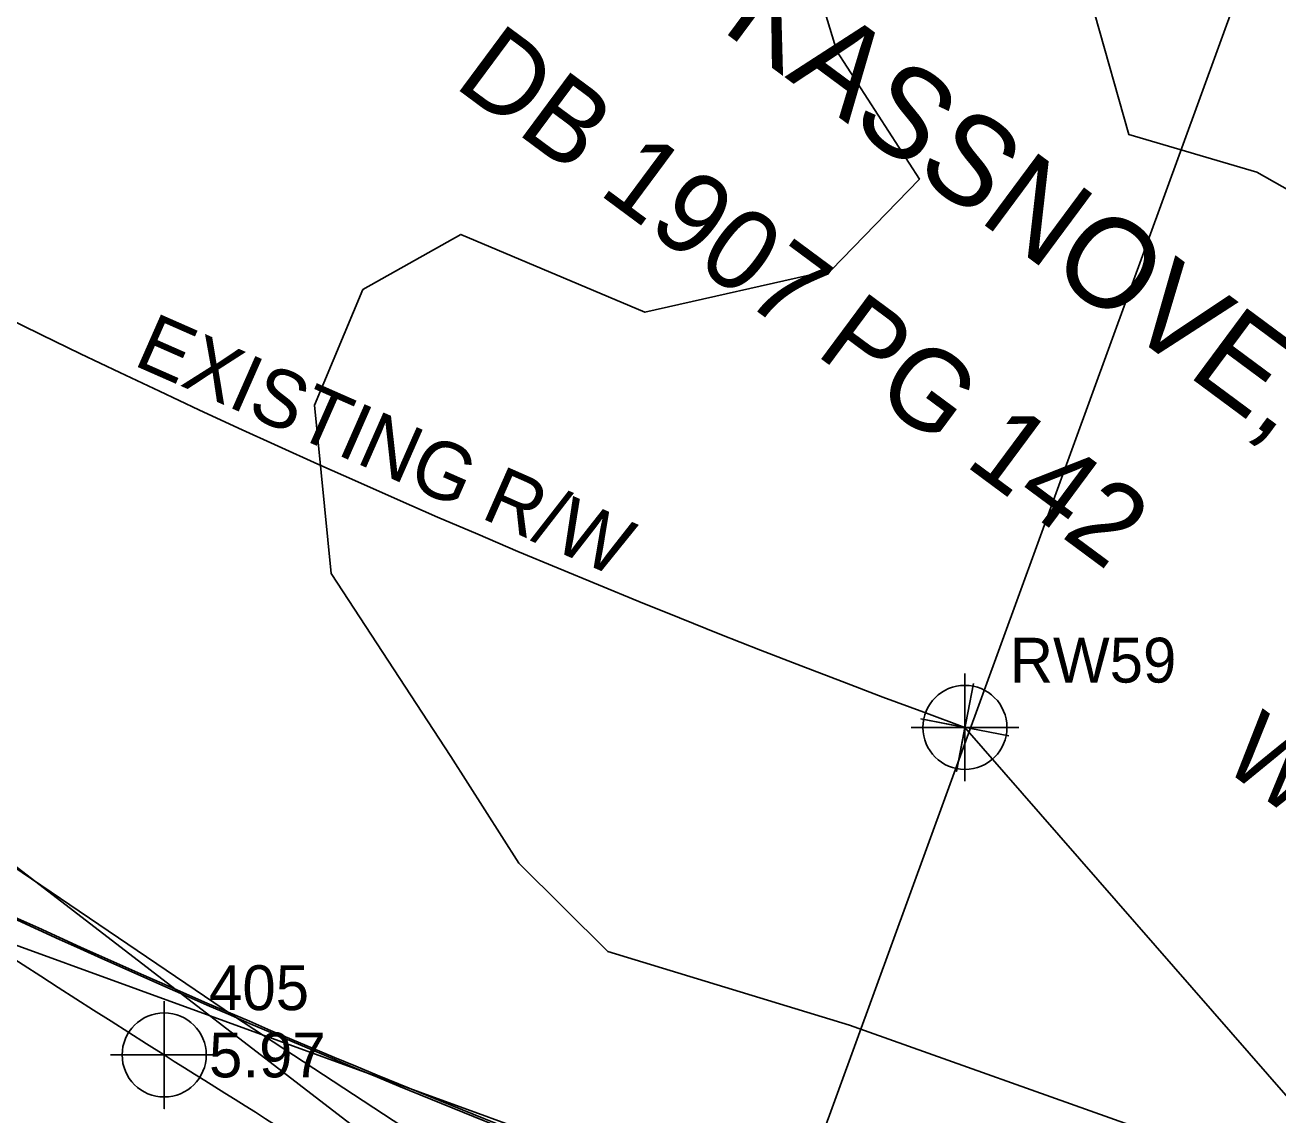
# Model space of a CAD drawing. Extents: x 2597630 to 2605918, y 617194 to 635093.
# Drawn here: x 2605095.9 to 2605165.7, y 618524 to 618584.8 of the extents above; entities that cross this region are included whole.
import ezdxf

# ---------------------------------------------------------------- set-up
doc = ezdxf.new("R2010")
doc.units = 0
for name, color, linetype in [('COGO Default Chain', 7, 'Continuous'), ('COGO Default Curve', 7, 'Continuous'), ('Cogo Default Point CELL', 7, 'Continuous'), ('COGO Default Point Number', 7, 'Continuous'), ('Exist Horizontal Alignment', 7, 'Continuous'), ('Exist Property Corner CELL', 7, 'Continuous'), ('Exist Property Deed Book Text', 7, 'Continuous'), ('Exist Property Owner Text', 7, 'Continuous'), ('Exist Right of Way Line', 7, 'Continuous'), ('Exist Right of Way Line Text', 7, 'Continuous'), ('Exist Roads EOP', 7, 'Continuous'), ('Exist Roads EOP Cogo Elevation', 7, 'Continuous'), ('Exist Roads EOP Cogo Number', 7, 'Continuous'), ('Exist Roads EOP Cogo Point CELL', 7, 'Continuous'), ('Exist Utilities Telephone UG Cable SUE LOS C', 7, 'Continuous'), ('Exist Vegetation Woods Line', 7, 'Continuous'), ('Exist Vegetation Woods Line Text', 7, 'Continuous'), ('Raster_Level_3', 7, 'Continuous')]:
    doc.layers.add(name, color=color, linetype=linetype)

# ---------------------------------------------------------------- blocks, each defined once
blk = doc.blocks.new('EXIST ROADS EOP COGO POINT')
at = {"layer": 'Exist Roads EOP Cogo Point CELL'}
blk.add_lwpolyline([(0, 0.06), (0, -0.06), (0, 0), (0.06, 0), (-0.06, 0)], dxfattribs=at)
blk.add_circle((0, 0), 0.0469, dxfattribs=at)
blk = doc.blocks.new('COGO DEFAULT POINT')
at = {"layer": 'Cogo Default Point CELL'}
for points in [[(0, 0.06), (0, 0)], [(-0.06, 0), (0, 0)], [(0, 0), (0.06, 0)], [(0, 0), (0, -0.06)]]:
    blk.add_lwpolyline(points, dxfattribs=at)
blk.add_circle((0, 0), 0.0469, dxfattribs=at)

msp = doc.modelspace()

# ---------------------------------------------------------------- linework, layer by layer
at = {"layer": 'COGO Default Chain'}
for p, q in [((2604635.42, 618891.582), (2605209.537, 618450.053)), ((2604635.42, 618891.582), (2605209.537, 618450.053)), ((2605081.924, 618538.367), (2605135.708, 618518.808)), ((2605081.924, 618538.367), (2605135.708, 618518.808)), ((2605081.924, 618538.367), (2605135.708, 618518.808))]:
    msp.add_line(p, q, dxfattribs=at)
msp.add_arc((2605334.316, 619054.493), 571.893, 233.44825, 249.95735, dxfattribs=at)
msp.add_arc((2605334.316, 619054.493), 571.893, 233.44825, 249.95735, dxfattribs=at)
msp.add_arc((2605334.316, 619054.493), 571.893, 233.44825, 249.95735, dxfattribs=at)
at = {"layer": 'COGO Default Curve'}
msp.add_arc((2605334.316, 619054.493), 571.893, 233.44825, 249.95735, dxfattribs=at)
msp.add_arc((2605334.316, 619054.493), 571.893, 233.44825, 249.95735, dxfattribs=at)
at = {"layer": 'Exist Horizontal Alignment'}
msp.add_arc((2605334.316, 619054.493), 571.893, 233.44825, 249.95735, dxfattribs=at)
at = {"layer": 'Exist Property Corner CELL'}
msp.add_line((2605148.26, 618545.632), (2605148.26, 618545.632), dxfattribs=at)
msp.add_lwpolyline([(2605150.714, 618545.154), (2605145.806, 618546.109), (2605148.26, 618545.632), (2605147.783, 618543.178), (2605148.738, 618548.086)], dxfattribs=at)
at = {"layer": 'Exist Right of Way Line'}
msp.add_line((2605148.26, 618545.632), (2605178.049, 618511.477), dxfattribs=at)
msp.add_arc((2605334.316, 619054.493), 541.808, 233.44825, 249.91603, dxfattribs=at)
at = {"layer": 'Exist Roads EOP'}
for points in [[(2604973.794, 618621.175), (2605003.899, 618598.528), (2605046.196, 618567.408), (2605072.515, 618548.047), (2605103.618, 618527.364), (2605140.117, 618505.161), (2605178.033, 618485.562), (2605220.739, 618472.458), (2605259.093, 618465.195), (2605301.774, 618462.969), (2605350.348, 618466.747), (2605390.569, 618472.395), (2605430.003, 618479.657), (2605472.601, 618488.42), (2605517.963, 618498.678), (2605555.274, 618508.222)], [(2605554.931, 618488.691), (2605518.323, 618479.552), (2605476.771, 618470.314), (2605429.068, 618460.66), (2605388.393, 618453.139), (2605342.247, 618446.788), (2605297.978, 618443.933), (2605250.493, 618446.948), (2605224.746, 618451.291), (2605188.067, 618461.914), (2605143.175, 618481.98), (2605101.821, 618506.05), (2605057.725, 618535.842), (2605018.828, 618564.087), (2604984.62, 618589.304), (2604956.97, 618610.183)]]:
    msp.add_spline(points, degree=3, dxfattribs=at)
at = {"layer": 'Exist Utilities Telephone UG Cable SUE LOS C'}
msp.add_lwpolyline([(2604704.632, 618797.902), (2604709.253, 618799.967), (2604746.093, 618830.902), (2604769.465, 618803.801), (2604789.101, 618780.394), (2604811.521, 618758.153), (2604839.523, 618732.525), (2604857.937, 618716.819), (2604890.546, 618690.254), (2604917.08, 618668.966), (2604949.989, 618644.104), (2604978.651, 618623.009), (2605029.128, 618585.555), (2605062.936, 618559.757), (2605107.482, 618529.542), (2605127.562, 618516.387), (2605160.551, 618498.208), (2605196.169, 618483.139), (2605231.309, 618473.571), (2605271.708, 618467.352), (2605299.025, 618467.352), (2605327.232, 618467.352), (2605372.412, 618473.385), (2605472.154, 618492.39)], dxfattribs=at)
at = {"layer": 'Exist Vegetation Woods Line'}
for points in [[(2605114.695, 618570.046), (2605120.152, 618573.13), (2605130.424, 618568.782), (2605140.796, 618571.139), (2605145.722, 618576.217), (2605141.112, 618583.352), (2605138.27, 618592.715), (2605142.058, 618600.277), (2605154.829, 618602.771), (2605155.857, 618594.281), (2605155.49, 618585.469), (2605157.393, 618578.694), (2605164.529, 618576.6), (2605173.309, 618571.628)], [(2605179.291, 618519.885), (2605158.53, 618523.075), (2605141.829, 618529.028), (2605128.359, 618533.128), (2605123.382, 618538.056), (2605119.59, 618544.003), (2605112.932, 618554.209), (2605111.99, 618563.601), (2605114.695, 618570.046)]]:
    msp.add_lwpolyline(points, dxfattribs=at)
at = {"layer": 'Raster_Level_3'}
msp.add_line((2605138.292, 618517.379), (2605333.954, 619054.76), dxfattribs=at)
msp.add_arc((2605333.954, 619054.76), 571.893, 233.49328, 249.99328, dxfattribs=at)

# ---------------------------------------------------------------- block references
at = {"layer": 'Cogo Default Point CELL', "xscale": 50, "yscale": 50}
msp.add_blockref('COGO DEFAULT POINT', (2605148.26, 618545.632), dxfattribs=at)
at = {"layer": 'Exist Roads EOP Cogo Point CELL', "xscale": 50, "yscale": 50}
msp.add_blockref('EXIST ROADS EOP COGO POINT', (2605103.618, 618527.364), dxfattribs=at)
msp.add_blockref('EXIST ROADS EOP COGO POINT', (2605103.618, 618527.364), dxfattribs=at)

# ---------------------------------------------------------------- texts
at = {"layer": 'COGO Default Point Number'}
msp.add_text('RW59', height=2.5, dxfattribs=at).set_placement((2605150.76, 618548.132))
at = {"layer": 'Exist Property Deed Book Text'}
msp.add_text('DB 1907 PG 142', height=4.5, rotation=323.44825, dxfattribs=at).set_placement((2605119.693, 618581.417))
at = {"layer": 'Exist Property Owner Text'}
msp.add_text('JONATHAN KASSNOVE, et al', height=5, rotation=323.44825, dxfattribs=at).set_placement((2605104.163, 618607.136))
at = {"layer": 'Exist Right of Way Line Text'}
msp.add_text('EXISTING R/W', height=3.2, rotation=336.23801, dxfattribs=at).set_placement((2605101.823, 618565.871))
at = {"layer": 'Exist Roads EOP Cogo Elevation'}
msp.add_text('5.97', height=2.5, dxfattribs=at).set_placement((2605106.118, 618526.114))
at = {"layer": 'Exist Roads EOP Cogo Number'}
msp.add_text('405', height=2.5, dxfattribs=at).set_placement((2605106.118, 618529.864))
at = {"layer": 'Exist Vegetation Woods Line Text'}
msp.add_text('WOODED', height=4, rotation=323.44825, dxfattribs=at).set_placement((2605162.451, 618543.506))

doc.saveas('drawing.dxf')
